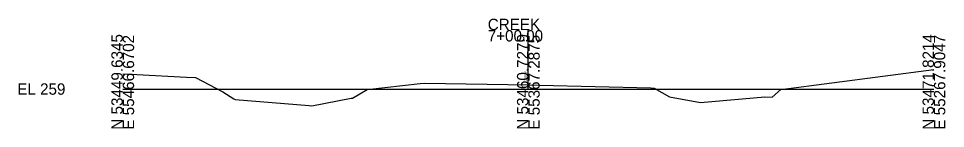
# Model space of a CAD drawing. Extents: x 7498 to 7727, y 91719 to 100242.
# Drawn here: x 7498.3 to 7726.8, y 92719.2 to 92746.2 of the extents above; entities that cross this region are included whole.
import ezdxf

# ---------------------------------------------------------------- set-up
doc = ezdxf.new("R2010")
doc.units = 0
for name, color, linetype in [('Level 10', 7, 'Continuous'), ('Level 60', 7, 'Continuous'), ('Level 63', 7, 'Continuous')]:
    doc.layers.add(name, color=color, linetype=linetype)

msp = doc.modelspace()

# ---------------------------------------------------------------- linework, layer by layer
at = {"layer": 'Level 60'}
for p, q in [((7523.99, 92732.6), (7526.28, 92732.5)), ((7526.28, 92732.5), (7527.5, 92732.43)), ((7527.5, 92732.43), (7539.67, 92731.81)), ((7686.21, 92728.72), (7723.99, 92733.68)), ((7539.67, 92731.81), (7541.95, 92731.67)), ((7541.95, 92731.67), (7548.69, 92728.19)), ((7584.27, 92728.73), (7597.33, 92730.25)), ((7597.33, 92730.25), (7598.45, 92730.27)), ((7598.45, 92730.27), (7624.05, 92729.89)), ((7548.69, 92728.19), (7551.36, 92726.48)), ((7580.63, 92726.64), (7584.27, 92728.73)), ((7624.05, 92729.89), (7626.75, 92729.82)), ((7626.75, 92729.82), (7654.16, 92729.12)), ((7654.16, 92729.12), (7655.04, 92729.1)), ((7655.04, 92729.1), (7658.82, 92726.9)), ((7684.09, 92726.85), (7686.21, 92728.72)), ((7551.36, 92726.48), (7551.72, 92726.28)), ((7551.72, 92726.28), (7569.96, 92724.8)), ((7570.64, 92724.75), (7580.3, 92726.58)), ((7580.3, 92726.58), (7580.63, 92726.64)), ((7658.82, 92726.9), (7666.43, 92725.5)), ((7666.43, 92725.5), (7682.31, 92726.91)), ((7682.31, 92726.91), (7684.09, 92726.85)), ((7569.96, 92724.8), (7570.64, 92724.75))]:
    msp.add_line(p, q, dxfattribs=at)
at = {"layer": 'Level 63'}
for p, q in [((7623.99, 92728.85), (7623.99, 92743.35)), ((7523.99, 92728.85), (7623.99, 92728.85)), ((7623.99, 92728.85), (7723.99, 92728.85))]:
    msp.add_line(p, q, dxfattribs=at)

# ---------------------------------------------------------------- texts
at = {"layer": 'Level 10'}
msp.add_text('260.04', height=0.6, rotation=90, dxfattribs=at).set_placement((7623.59, 92730.89))
at = {"layer": 'Level 63'}
for s, p in [('CREEK', (7613.99, 92743.35)), ('7+00.00', (7613.99, 92740.55)), ('EL 259', (7497.99, 92727.45))]:
    msp.add_text(s, height=2.8, dxfattribs=at).set_placement(p)
for s, p in [('N 53449.6345', (7523.99, 92718.85)), ('E 55466.6702', (7526.79, 92718.85)), ('N 53460.7279', (7623.99, 92718.85)), ('E 55367.2875', (7626.79, 92718.85)), ('N 53471.8214', (7723.99, 92718.85)), ('E 55267.9047', (7726.79, 92718.85))]:
    msp.add_text(s, height=2.8, rotation=90, dxfattribs=at).set_placement(p)

doc.saveas('drawing.dxf')
